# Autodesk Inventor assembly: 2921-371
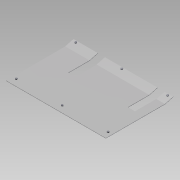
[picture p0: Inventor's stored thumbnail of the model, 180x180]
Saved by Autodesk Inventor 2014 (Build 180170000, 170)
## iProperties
Company: NHTSA/VRTC
Created: 2012-03
Part Number: 2921-371
Document SubType Name: Assembly
Designer: Mike Vanvoorhis
Project: CHILD SIDE IMPACT SLED
Description: SEAT BOTTOM CUSHION MTG. PLATE ASS'Y.
Mass: 1863.56 g
Surface Area: 6873.78 cm^2
Volume: 678.807 cm^3
Density: 2.74534 g/cm^3
DESIGN DATE: 2012-11-05
Title: Seat Bottom Cushion  Mounting Plate Ass'y.
Subject: Child Sid Impact Sled
Author: Dave Walker
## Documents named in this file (3)
- B:\VRTC_DWG\BIO\Non-P572\Child Side-Frontal Impact Sled\Side Impact Sled\Seat_Bottom_Cushion_Mounting_Plate_Assembly.iam
- B:\VRTC_DWG\BIO\Non-P572\Child Side-Frontal Impact Sled\Side Impact Sled\Seat_Bottom_Cushion_Mounting_Plate.ipt
- B:\VRTC_DWG\Inventor Support Files\Content Center\en-US\ANSI ASME B18.2.1(2)\ANSI_ASME B18.2.1 - 1_4-28 UNF - 0.875(2).ipt
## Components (7 placed, 2 different names)
1. Seat_Bottom_Cushion_Mounting_Plate:1 — Insert:10, Insert:11, Insert:12, Insert:13, Insert:14, Insert:15
2. Hex Bolt - Inch 1/4-28 UNF - 0.875:1 — Insert:11
3. Hex Bolt - Inch 1/4-28 UNF - 0.875:2 — Insert:10
4. Hex Bolt - Inch 1/4-28 UNF - 0.875:3 — Insert:12
5. Hex Bolt - Inch 1/4-28 UNF - 0.875:6 — Insert:13
6. Hex Bolt - Inch 1/4-28 UNF - 0.875:8 — Insert:14
7. Hex Bolt - Inch 1/4-28 UNF - 0.875:9 — Insert:15
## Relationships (6: Insert 6)
- Insert:10: Seat_Bottom_Cushion_Mounting_Plate:1 ↔ Hex Bolt - Inch 1/4-28 UNF - 0.875:2
- Insert:11: Seat_Bottom_Cushion_Mounting_Plate:1 ↔ Hex Bolt - Inch 1/4-28 UNF - 0.875:1
- Insert:12: Seat_Bottom_Cushion_Mounting_Plate:1 ↔ Hex Bolt - Inch 1/4-28 UNF - 0.875:3
- Insert:13: Seat_Bottom_Cushion_Mounting_Plate:1 ↔ Hex Bolt - Inch 1/4-28 UNF - 0.875:6
- Insert:14: Seat_Bottom_Cushion_Mounting_Plate:1 ↔ Hex Bolt - Inch 1/4-28 UNF - 0.875:8
- Insert:15: Seat_Bottom_Cushion_Mounting_Plate:1 ↔ Hex Bolt - Inch 1/4-28 UNF - 0.875:9
